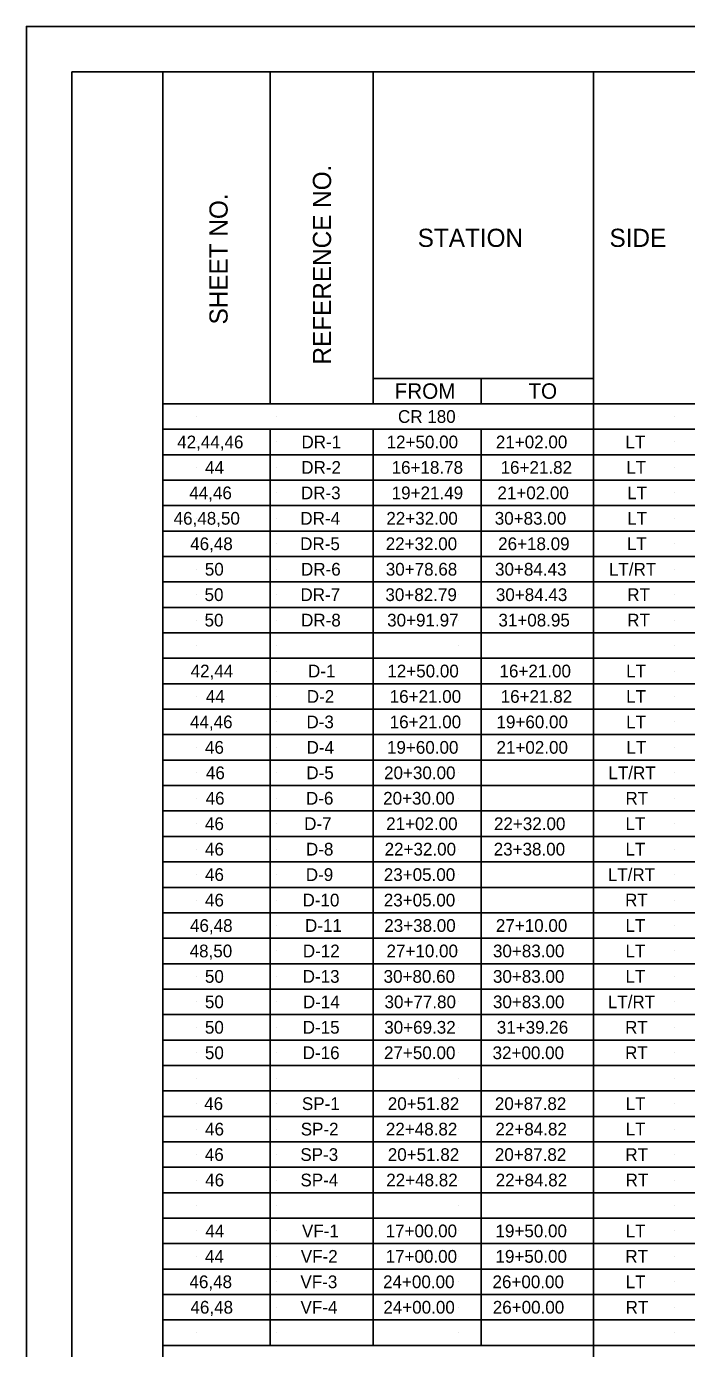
# Model space of a CAD drawing. Extents: x 2073163.9 to 2073197.9, y 634076.5 to 634098.5.
# Drawn here: x 2073163.95 to 2073171.21, y 634084 to 634098.55 of the extents above; entities that cross this region are included whole.
import ezdxf

# ---------------------------------------------------------------- set-up
doc = ezdxf.new("R2010")
doc.units = 0
for name, color, linetype in [('SH_Border', 7, 'Continuous'), ('SH_Cut_Line', 7, 'Continuous'), ('SH_Data', 7, 'Continuous'), ('SH_Text', 7, 'Continuous')]:
    doc.layers.add(name, color=color, linetype=linetype)

msp = doc.modelspace()

# ---------------------------------------------------------------- linework, layer by layer
at = {"layer": 'SH_Border'}
msp.add_line((2073165.446, 634094.398), (2073165.446, 634098.05), dxfattribs=at)
for points in [[(2073164.446, 634098.05), (2073165.446, 634098.05), (2073165.446, 634077.05), (2073164.446, 634077.05)], [(2073165.446, 634098.05), (2073197.446, 634098.05), (2073197.446, 634077.05), (2073165.446, 634077.05)]]:
    msp.add_lwpolyline(points, close=True, dxfattribs=at)
at = {"layer": 'SH_Cut_Line'}
msp.add_lwpolyline([(2073163.946, 634076.55), (2073197.946, 634076.55), (2073197.946, 634098.55), (2073163.946, 634098.55)], close=True, dxfattribs=at)
at = {"layer": 'SH_Data'}
for p, q in [((2073166.627, 634094.398), (2073166.627, 634098.05)), ((2073167.759, 634094.398), (2073167.759, 634098.05)), ((2073170.183, 634077.598), (2073170.183, 634098.05)), ((2073165.446, 634094.398), (2073195.946, 634094.398)), ((2073165.821, 634094.258), (2073165.821, 634094.258)), ((2073166.696, 634094.258), (2073166.696, 634094.258)), ((2073168.696, 634094.258), (2073168.696, 634094.258)), ((2073171.071, 634094.258), (2073171.071, 634094.258)), ((2073165.44, 634094.118), (2073195.948, 634094.118)), ((2073166.627, 634084.038), (2073166.627, 634094.118)), ((2073167.759, 634084.038), (2073167.759, 634094.118)), ((2073165.821, 634093.978), (2073165.821, 634093.978)), ((2073166.696, 634093.978), (2073166.696, 634093.978)), ((2073168.696, 634093.978), (2073168.696, 634093.978)), ((2073171.071, 634093.978), (2073171.071, 634093.978)), ((2073165.45, 634093.838), (2073195.947, 634093.838)), ((2073165.821, 634093.698), (2073165.821, 634093.698)), ((2073166.696, 634093.698), (2073166.696, 634093.698)), ((2073168.696, 634093.698), (2073168.696, 634093.698)), ((2073171.071, 634093.698), (2073171.071, 634093.698)), ((2073165.45, 634093.558), (2073195.947, 634093.558)), ((2073165.821, 634093.418), (2073165.821, 634093.418)), ((2073166.696, 634093.418), (2073166.696, 634093.418)), ((2073168.696, 634093.418), (2073168.696, 634093.418)), ((2073171.071, 634093.418), (2073171.071, 634093.418)), ((2073165.447, 634093.278), (2073195.949, 634093.278)), ((2073165.821, 634093.138), (2073165.821, 634093.138)), ((2073166.696, 634093.138), (2073166.696, 634093.138)), ((2073168.696, 634093.138), (2073168.696, 634093.138)), ((2073171.071, 634093.138), (2073171.071, 634093.138)), ((2073165.444, 634092.998), (2073195.947, 634092.998)), ((2073165.821, 634092.858), (2073165.821, 634092.858)), ((2073166.696, 634092.858), (2073166.696, 634092.858)), ((2073168.696, 634092.858), (2073168.696, 634092.858)), ((2073171.071, 634092.858), (2073171.071, 634092.858)), ((2073165.454, 634092.718), (2073195.947, 634092.718)), ((2073165.821, 634092.578), (2073165.821, 634092.578)), ((2073166.696, 634092.578), (2073166.696, 634092.578)), ((2073168.696, 634092.578), (2073168.696, 634092.578)), ((2073171.071, 634092.578), (2073171.071, 634092.578)), ((2073165.45, 634092.438), (2073195.943, 634092.438)), ((2073165.821, 634092.298), (2073165.821, 634092.298)), ((2073166.696, 634092.298), (2073166.696, 634092.298)), ((2073168.696, 634092.298), (2073168.696, 634092.298)), ((2073171.071, 634092.298), (2073171.071, 634092.298)), ((2073165.448, 634092.158), (2073195.943, 634092.158)), ((2073165.821, 634092.018), (2073165.821, 634092.018)), ((2073166.696, 634092.018), (2073166.696, 634092.018)), ((2073168.696, 634092.018), (2073168.696, 634092.018)), ((2073171.071, 634092.018), (2073171.071, 634092.018)), ((2073165.448, 634091.878), (2073195.943, 634091.878)), ((2073165.821, 634091.738), (2073165.821, 634091.738)), ((2073166.696, 634091.738), (2073166.696, 634091.738)), ((2073168.696, 634091.738), (2073168.696, 634091.738)), ((2073171.071, 634091.738), (2073171.071, 634091.738)), ((2073165.448, 634091.598), (2073195.948, 634091.598)), ((2073165.821, 634091.458), (2073165.821, 634091.458)), ((2073166.696, 634091.458), (2073166.696, 634091.458)), ((2073168.696, 634091.458), (2073168.696, 634091.458)), ((2073171.071, 634091.458), (2073171.071, 634091.458)), ((2073165.451, 634091.318), (2073195.939, 634091.318)), ((2073165.451, 634091.318), (2073195.944, 634091.318)), ((2073165.821, 634091.178), (2073165.821, 634091.178)), ((2073166.696, 634091.178), (2073166.696, 634091.178)), ((2073168.696, 634091.178), (2073168.696, 634091.178)), ((2073171.071, 634091.178), (2073171.071, 634091.178)), ((2073165.448, 634091.038), (2073195.944, 634091.038)), ((2073165.821, 634090.898), (2073165.821, 634090.898)), ((2073166.696, 634090.898), (2073166.696, 634090.898)), ((2073168.696, 634090.898), (2073168.696, 634090.898)), ((2073171.071, 634090.898), (2073171.071, 634090.898)), ((2073165.445, 634090.758), (2073195.942, 634090.758)), ((2073165.821, 634090.618), (2073165.821, 634090.618)), ((2073166.696, 634090.618), (2073166.696, 634090.618)), ((2073168.696, 634090.618), (2073168.696, 634090.618)), ((2073171.071, 634090.618), (2073171.071, 634090.618)), ((2073165.442, 634090.478), (2073195.946, 634090.478)), ((2073165.821, 634090.338), (2073165.821, 634090.338)), ((2073166.696, 634090.338), (2073166.696, 634090.338)), ((2073168.696, 634090.338), (2073168.696, 634090.338)), ((2073171.071, 634090.338), (2073171.071, 634090.338)), ((2073165.442, 634090.198), (2073195.946, 634090.198)), ((2073165.821, 634090.058), (2073165.821, 634090.058)), ((2073166.696, 634090.058), (2073166.696, 634090.058)), ((2073168.696, 634090.058), (2073168.696, 634090.058)), ((2073171.071, 634090.058), (2073171.071, 634090.058)), ((2073165.446, 634089.918), (2073195.946, 634089.918)), ((2073165.821, 634089.778), (2073165.821, 634089.778)), ((2073166.696, 634089.778), (2073166.696, 634089.778)), ((2073168.696, 634089.778), (2073168.696, 634089.778)), ((2073171.071, 634089.778), (2073171.071, 634089.778)), ((2073165.446, 634089.638), (2073195.946, 634089.638)), ((2073165.821, 634089.498), (2073165.821, 634089.498)), ((2073166.696, 634089.498), (2073166.696, 634089.498)), ((2073168.696, 634089.498), (2073168.696, 634089.498)), ((2073171.071, 634089.498), (2073171.071, 634089.498)), ((2073165.446, 634089.358), (2073195.946, 634089.358)), ((2073165.821, 634089.218), (2073165.821, 634089.218)), ((2073166.696, 634089.218), (2073166.696, 634089.218)), ((2073168.696, 634089.218), (2073168.696, 634089.218)), ((2073171.071, 634089.218), (2073171.071, 634089.218)), ((2073165.446, 634089.078), (2073195.946, 634089.078)), ((2073165.821, 634088.938), (2073165.821, 634088.938)), ((2073166.696, 634088.938), (2073166.696, 634088.938)), ((2073168.696, 634088.938), (2073168.696, 634088.938)), ((2073171.071, 634088.938), (2073171.071, 634088.938)), ((2073165.446, 634088.798), (2073195.946, 634088.798)), ((2073165.821, 634088.658), (2073165.821, 634088.658)), ((2073166.696, 634088.658), (2073166.696, 634088.658)), ((2073168.696, 634088.658), (2073168.696, 634088.658)), ((2073171.071, 634088.658), (2073171.071, 634088.658)), ((2073165.446, 634088.518), (2073195.946, 634088.518)), ((2073165.821, 634088.378), (2073165.821, 634088.378)), ((2073166.696, 634088.378), (2073166.696, 634088.378)), ((2073168.696, 634088.378), (2073168.696, 634088.378)), ((2073171.071, 634088.378), (2073171.071, 634088.378)), ((2073165.446, 634088.238), (2073195.946, 634088.238)), ((2073165.821, 634088.098), (2073165.821, 634088.098)), ((2073166.696, 634088.098), (2073166.696, 634088.098)), ((2073168.696, 634088.098), (2073168.696, 634088.098)), ((2073171.071, 634088.098), (2073171.071, 634088.098)), ((2073165.446, 634087.958), (2073195.946, 634087.958)), ((2073165.821, 634087.818), (2073165.821, 634087.818)), ((2073166.696, 634087.818), (2073166.696, 634087.818)), ((2073168.696, 634087.818), (2073168.696, 634087.818)), ((2073171.071, 634087.818), (2073171.071, 634087.818)), ((2073165.446, 634087.678), (2073195.946, 634087.678)), ((2073165.821, 634087.538), (2073165.821, 634087.538)), ((2073166.696, 634087.538), (2073166.696, 634087.538)), ((2073168.696, 634087.538), (2073168.696, 634087.538)), ((2073171.071, 634087.538), (2073171.071, 634087.538)), ((2073165.446, 634087.398), (2073195.946, 634087.398)), ((2073165.821, 634087.258), (2073165.821, 634087.258)), ((2073166.696, 634087.258), (2073166.696, 634087.258)), ((2073168.696, 634087.258), (2073168.696, 634087.258)), ((2073171.071, 634087.258), (2073171.071, 634087.258)), ((2073165.446, 634087.118), (2073195.946, 634087.118)), ((2073165.821, 634086.978), (2073165.821, 634086.978)), ((2073166.696, 634086.978), (2073166.696, 634086.978)), ((2073168.696, 634086.978), (2073168.696, 634086.978)), ((2073171.071, 634086.978), (2073171.071, 634086.978)), ((2073165.446, 634086.838), (2073195.946, 634086.838)), ((2073165.821, 634086.698), (2073165.821, 634086.698)), ((2073166.696, 634086.698), (2073166.696, 634086.698)), ((2073168.696, 634086.698), (2073168.696, 634086.698)), ((2073171.071, 634086.698), (2073171.071, 634086.698)), ((2073165.446, 634086.558), (2073195.946, 634086.558)), ((2073165.821, 634086.418), (2073165.821, 634086.418)), ((2073166.696, 634086.418), (2073166.696, 634086.418)), ((2073168.696, 634086.418), (2073168.696, 634086.418)), ((2073171.071, 634086.418), (2073171.071, 634086.418)), ((2073165.446, 634086.278), (2073195.946, 634086.278)), ((2073165.446, 634085.998), (2073195.946, 634085.998)), ((2073165.821, 634086.138), (2073165.821, 634086.138)), ((2073166.696, 634086.138), (2073166.696, 634086.138)), ((2073168.696, 634086.138), (2073168.696, 634086.138)), ((2073171.071, 634086.138), (2073171.071, 634086.138)), ((2073165.821, 634085.858), (2073165.821, 634085.858)), ((2073166.696, 634085.858), (2073166.696, 634085.858)), ((2073168.696, 634085.858), (2073168.696, 634085.858)), ((2073171.071, 634085.858), (2073171.071, 634085.858)), ((2073165.446, 634085.718), (2073195.946, 634085.718)), ((2073165.821, 634085.578), (2073165.821, 634085.578)), ((2073166.696, 634085.578), (2073166.696, 634085.578)), ((2073168.696, 634085.578), (2073168.696, 634085.578)), ((2073171.071, 634085.578), (2073171.071, 634085.578)), ((2073165.446, 634085.438), (2073195.946, 634085.438)), ((2073165.821, 634085.298), (2073165.821, 634085.298)), ((2073166.696, 634085.298), (2073166.696, 634085.298)), ((2073168.696, 634085.298), (2073168.696, 634085.298)), ((2073171.071, 634085.298), (2073171.071, 634085.298)), ((2073165.446, 634085.158), (2073195.946, 634085.158)), ((2073165.821, 634085.018), (2073165.821, 634085.018)), ((2073166.696, 634085.018), (2073166.696, 634085.018)), ((2073168.696, 634085.018), (2073168.696, 634085.018)), ((2073171.071, 634085.018), (2073171.071, 634085.018)), ((2073165.446, 634084.878), (2073195.946, 634084.878)), ((2073165.821, 634084.738), (2073165.821, 634084.738)), ((2073166.696, 634084.738), (2073166.696, 634084.738)), ((2073168.696, 634084.738), (2073168.696, 634084.738)), ((2073171.071, 634084.738), (2073171.071, 634084.738)), ((2073165.446, 634084.598), (2073195.946, 634084.598)), ((2073165.821, 634084.458), (2073165.821, 634084.458)), ((2073166.696, 634084.458), (2073166.696, 634084.458)), ((2073168.696, 634084.458), (2073168.696, 634084.458)), ((2073171.071, 634084.458), (2073171.071, 634084.458)), ((2073165.446, 634084.318), (2073195.946, 634084.318)), ((2073165.821, 634084.178), (2073165.821, 634084.178)), ((2073166.696, 634084.178), (2073166.696, 634084.178)), ((2073168.696, 634084.178), (2073168.696, 634084.178)), ((2073171.071, 634084.178), (2073171.071, 634084.178)), ((2073165.446, 634084.038), (2073195.946, 634084.038))]:
    msp.add_line(p, q, dxfattribs=at)
at = {"layer": 'SH_Text'}
for p, q in [((2073167.759, 634094.678), (2073170.183, 634094.678)), ((2073168.949, 634094.678), (2073168.949, 634094.398)), ((2073168.949, 634094.118), (2073168.949, 634084.038))]:
    msp.add_line(p, q, dxfattribs=at)

# ---------------------------------------------------------------- texts
at = {"layer": 'SH_Data'}
for s, p in [('REFERENCE NO.', (2073167.297, 634094.83)), ('SHEET NO.', (2073166.159, 634095.271))]:
    msp.add_text(s, height=0.2, rotation=90, dxfattribs=at).set_placement(p)
for s, p in [('STATION', (2073168.25, 634096.124)), ('SIDE', (2073170.36, 634096.124))]:
    msp.add_text(s, height=0.2, dxfattribs=at).set_placement(p)
at = {"layer": 'SH_Text'}
for s, p in [('FROM', (2073167.996, 634094.453)), ('TO', (2073169.468, 634094.453))]:
    msp.add_text(s, height=0.17, dxfattribs=at).set_placement(p)
for s, p in [('CR 180', (2073168.033, 634094.188)), ('42,44,46', (2073165.604, 634093.908)), ('DR-1', (2073166.971, 634093.908)), ('12+50.00', (2073167.908, 634093.908)), ('21+02.00', (2073169.11, 634093.908)), ('LT', (2073170.535, 634093.908)), ('44', (2073165.911, 634093.628)), ('DR-2', (2073166.969, 634093.628)), ('16+18.78', (2073167.963, 634093.628)), ('16+21.82', (2073169.162, 634093.628)), ('LT', (2073170.545, 634093.628)), ('44,46', (2073165.737, 634093.348)), ('DR-3', (2073166.965, 634093.348)), ('19+21.49', (2073167.964, 634093.348)), ('21+02.00', (2073169.127, 634093.348)), ('LT', (2073170.555, 634093.348)), ('46,48,50', (2073165.565, 634093.068)), ('DR-4', (2073166.959, 634093.068)), ('22+32.00', (2073167.905, 634093.068)), ('30+83.00', (2073169.098, 634093.068)), ('LT', (2073170.555, 634093.068)), ('46,48', (2073165.747, 634092.788)), ('DR-5', (2073166.957, 634092.788)), ('22+32.00', (2073167.898, 634092.788)), ('26+18.09', (2073169.135, 634092.788)), ('LT', (2073170.552, 634092.788)), ('50', (2073165.908, 634092.508)), ('DR-6', (2073166.966, 634092.508)), ('30+78.68', (2073167.899, 634092.508)), ('30+84.43', (2073169.101, 634092.508)), ('LT/RT', (2073170.354, 634092.508)), ('50', (2073165.905, 634092.228)), ('DR-7', (2073166.96, 634092.228)), ('30+82.79', (2073167.895, 634092.228)), ('30+84.43', (2073169.11, 634092.228)), ('RT', (2073170.555, 634092.228)), ('50', (2073165.905, 634091.948)), ('DR-8', (2073166.967, 634091.948)), ('30+91.97', (2073167.914, 634091.948)), ('31+08.95', (2073169.138, 634091.948)), ('RT', (2073170.555, 634091.948)), ('42,44', (2073165.752, 634091.388)), ('D-1', (2073167.043, 634091.388)), ('12+50.00', (2073167.916, 634091.388)), ('16+21.00', (2073169.15, 634091.388)), ('LT', (2073170.543, 634091.388)), ('44', (2073165.919, 634091.108)), ('D-2', (2073167.03, 634091.108)), ('16+21.00', (2073167.942, 634091.108)), ('16+21.82', (2073169.163, 634091.108)), ('LT', (2073170.543, 634091.108)), ('44,46', (2073165.745, 634090.828)), ('D-3', (2073167.026, 634090.828)), ('16+21.00', (2073167.942, 634090.828)), ('19+60.00', (2073169.117, 634090.828)), ('LT', (2073170.543, 634090.828)), ('46', (2073165.91, 634090.548)), ('D-4', (2073167.028, 634090.548)), ('19+60.00', (2073167.912, 634090.548)), ('21+02.00', (2073169.117, 634090.548)), ('LT', (2073170.546, 634090.548)), ('46', (2073165.92, 634090.268)), ('D-5', (2073167.025, 634090.268)), ('20+30.00', (2073167.88, 634090.268)), ('LT/RT', (2073170.348, 634090.268)), ('46', (2073165.917, 634089.988)), ('D-6', (2073167.021, 634089.988)), ('20+30.00', (2073167.87, 634089.988)), ('RT', (2073170.536, 634089.988)), ('46', (2073165.91, 634089.708)), ('D-7', (2073167.001, 634089.708)), ('21+02.00', (2073167.903, 634089.708)), ('22+32.00', (2073169.089, 634089.708)), ('LT', (2073170.536, 634089.708)), ('46', (2073165.91, 634089.428)), ('D-8', (2073167.021, 634089.428)), ('22+32.00', (2073167.886, 634089.428)), ('23+38.00', (2073169.086, 634089.428)), ('LT', (2073170.536, 634089.428)), ('46', (2073165.91, 634089.148)), ('D-9', (2073167.019, 634089.148)), ('23+05.00', (2073167.877, 634089.148)), ('LT/RT', (2073170.342, 634089.148)), ('46', (2073165.91, 634088.868)), ('D-10', (2073166.983, 634088.868)), ('23+05.00', (2073167.877, 634088.868)), ('RT', (2073170.532, 634088.868)), ('46,48', (2073165.745, 634088.588)), ('D-11', (2073167.01, 634088.588)), ('23+38.00', (2073167.882, 634088.588)), ('27+10.00', (2073169.11, 634088.588)), ('LT', (2073170.536, 634088.588)), ('48,50', (2073165.741, 634088.308)), ('D-12', (2073166.986, 634088.308)), ('27+10.00', (2073167.907, 634088.308)), ('30+83.00', (2073169.078, 634088.308)), ('LT', (2073170.536, 634088.308)), ('50', (2073165.909, 634088.028)), ('D-13', (2073166.985, 634088.028)), ('30+80.60', (2073167.875, 634088.028)), ('30+83.00', (2073169.078, 634088.028)), ('LT', (2073170.536, 634088.028)), ('50', (2073165.909, 634087.748)), ('D-14', (2073166.987, 634087.748)), ('30+77.80', (2073167.885, 634087.748)), ('30+83.00', (2073169.078, 634087.748)), ('LT/RT', (2073170.342, 634087.748)), ('50', (2073165.909, 634087.468)), ('D-15', (2073166.985, 634087.468)), ('30+69.32', (2073167.882, 634087.468)), ('31+39.26', (2073169.12, 634087.468)), ('RT', (2073170.532, 634087.468)), ('50', (2073165.909, 634087.188)), ('D-16', (2073166.985, 634087.188)), ('27+50.00', (2073167.879, 634087.188)), ('32+00.00', (2073169.074, 634087.188)), ('RT', (2073170.532, 634087.188)), ('46', (2073165.901, 634086.628)), ('SP-1', (2073166.976, 634086.628)), ('20+51.82', (2073167.921, 634086.628)), ('20+87.82', (2073169.099, 634086.628)), ('LT', (2073170.538, 634086.628)), ('46', (2073165.911, 634086.348)), ('SP-2', (2073166.963, 634086.348)), ('22+48.82', (2073167.9, 634086.348)), ('22+84.82', (2073169.105, 634086.348)), ('LT', (2073170.538, 634086.348)), ('46', (2073165.908, 634086.068)), ('SP-3', (2073166.959, 634086.068)), ('20+51.82', (2073167.921, 634086.068)), ('20+87.82', (2073169.099, 634086.068)), ('RT', (2073170.534, 634086.068)), ('46', (2073165.912, 634085.788)), ('SP-4', (2073166.96, 634085.788)), ('22+48.82', (2073167.904, 634085.788)), ('22+84.82', (2073169.108, 634085.788)), ('RT', (2073170.537, 634085.788)), ('44', (2073165.914, 634085.228)), ('VF-1', (2073166.977, 634085.228)), ('17+00.00', (2073167.897, 634085.228)), ('19+50.00', (2073169.106, 634085.228)), ('LT', (2073170.538, 634085.228)), ('44', (2073165.91, 634084.948)), ('VF-2', (2073166.964, 634084.948)), ('17+00.00', (2073167.897, 634084.948)), ('19+50.00', (2073169.106, 634084.948)), ('RT', (2073170.534, 634084.948)), ('46,48', (2073165.739, 634084.668)), ('VF-3', (2073166.96, 634084.668)), ('24+00.00', (2073167.869, 634084.668)), ('26+00.00', (2073169.073, 634084.668)), ('LT', (2073170.538, 634084.668)), ('46,48', (2073165.75, 634084.388)), ('VF-4', (2073166.961, 634084.388)), ('24+00.00', (2073167.872, 634084.388)), ('26+00.00', (2073169.076, 634084.388)), ('RT', (2073170.537, 634084.388))]:
    msp.add_text(s, height=0.14, rotation=0.0001, dxfattribs=at).set_placement(p)

doc.saveas('drawing.dxf')
